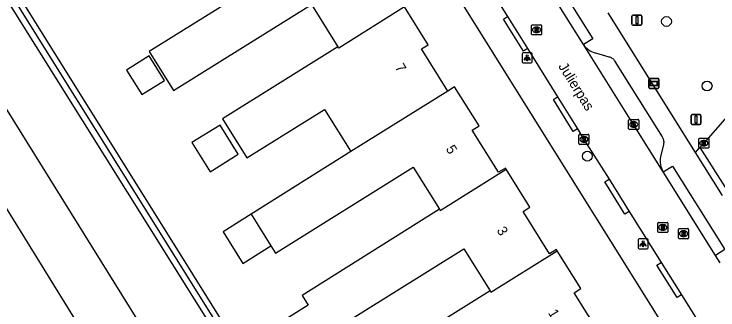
# Model space of a CAD drawing. Extents: x 158838 to 160074, y 386376 to 387776.
# Drawn here: x 159122.1 to 159192.2, y 386846.6 to 386876.1 of the extents above; entities that cross this region are included whole.
import ezdxf

# ---------------------------------------------------------------- set-up
doc = ezdxf.new("R2010")
doc.units = 0
for name, color, linetype in [('IMGEO_Afsluitpaal', 7, 'Continuous'), ('IMGEO_Berm_groen', 7, 'Continuous'), ('IMGEO_Boom', 7, 'Continuous'), ('IMGEO_Groenvoorziening', 7, 'Continuous'), ('IMGEO_Kolk', 7, 'Continuous'), ('IMGEO_Lichtpunt', 7, 'Continuous'), ('IMGEO_Openbare_ruimte_label', 7, 'Continuous'), ('IMGEO_Pand', 7, 'Continuous'), ('IMGEO_Pand_nummerreeks', 7, 'Continuous'), ('IMGEO_Rijbaan_lokaal_open', 7, 'Continuous'), ('IMGEO_Rioolput', 7, 'Continuous'), ('IMGEO_Straatnaambord', 7, 'Continuous'), ('IMGEO_Voetpad_open', 7, 'Continuous')]:
    doc.layers.add(name, color=color, linetype=linetype)

msp = doc.modelspace()

# ---------------------------------------------------------------- linework, layer by layer
at = {"layer": 'IMGEO_Afsluitpaal'}
for p, q in [((159183.612, 386875.093), (159183.612, 386875.893)), ((159183.612, 386875.893), (159183.612, 386875.093)), ((159183.712, 386875.993), (159184.502, 386875.993)), ((159184.502, 386875.993), (159183.712, 386875.993)), ((159184.602, 386875.893), (159184.602, 386875.093)), ((159184.602, 386875.093), (159184.602, 386875.893)), ((159184.502, 386874.993), (159183.712, 386874.993)), ((159183.712, 386874.993), (159184.502, 386874.993)), ((159189.493, 386865.198), (159189.493, 386865.998)), ((159189.493, 386865.998), (159189.493, 386865.198)), ((159189.593, 386866.098), (159190.383, 386866.098)), ((159190.383, 386866.098), (159189.593, 386866.098)), ((159190.483, 386865.998), (159190.483, 386865.198)), ((159190.483, 386865.198), (159190.483, 386865.998)), ((159190.383, 386865.098), (159189.593, 386865.098)), ((159189.593, 386865.098), (159190.383, 386865.098))]:
    msp.add_line(p, q, dxfattribs=at)
for points in [[(159184.032, 386875.868), (159184.182, 386875.868), (159184.182, 386875.118), (159184.032, 386875.118), (159184.032, 386875.868)], [(159189.913, 386865.973), (159190.063, 386865.973), (159190.063, 386865.223), (159189.913, 386865.223), (159189.913, 386865.973)]]:
    msp.add_lwpolyline(points, dxfattribs=at)
for centre, start, end in [((159183.712, 386875.893), 90, 180), ((159183.712, 386875.893), 90, 180), ((159184.502, 386875.893), 0, 90), ((159184.502, 386875.893), 360, 90), ((159183.712, 386875.093), 180, 270), ((159183.712, 386875.093), 180, 270), ((159184.502, 386875.093), 270, 0), ((159184.502, 386875.093), 270, 0), ((159189.593, 386865.998), 90, 180), ((159189.593, 386865.998), 90, 180), ((159190.383, 386865.998), 0, 90), ((159190.383, 386865.998), 360, 90), ((159189.593, 386865.198), 180, 270), ((159189.593, 386865.198), 180, 270), ((159190.383, 386865.198), 270, 0), ((159190.383, 386865.198), 270, 0)]:
    msp.add_arc(centre, 0.1, start, end, dxfattribs=at)
at = {"layer": 'IMGEO_Berm_groen'}
for points in [[(159123.048, 386814.194), (159142.528, 386822.4), (159089.158, 386908.868), (159070.867, 386896.72), (159109.025, 386833.71), (159123.048, 386814.194)], [(159096.401, 386906.705), (159148.14, 386823.428)]]:
    msp.add_lwpolyline(points, dxfattribs=at)
at = {"layer": 'IMGEO_Boom'}
for centre in [(159187.048, 386875.362), (159191.091, 386868.94), (159179.16, 386861.946)]:
    msp.add_circle(centre, 0.489, dxfattribs=at)
at = {"layer": 'IMGEO_Groenvoorziening'}
for points in [[(159153.383, 386826.367), (159102.052, 386908.422), (159101.832, 386908.935), (159101.604, 386909.612), (159101.437, 386910.307), (159101.332, 386911.014), (159101.291, 386911.728), (159101.315, 386912.442), (159101.402, 386913.152), (159101.551, 386913.851), (159101.763, 386914.534), (159102.035, 386915.195), (159102.365, 386915.829)], [(159102.915, 386915.575), (159102.608, 386914.992), (159102.355, 386914.384), (159102.156, 386913.756), (159102.015, 386913.113), (159101.932, 386912.46), (159101.907, 386911.802), (159101.941, 386911.144), (159102.034, 386910.492), (159102.185, 386909.851), (159102.393, 386909.226), (159102.615, 386908.705), (159154.046, 386826.389)], [(159154.526, 386826.749), (159103.157, 386908.962)]]:
    msp.add_lwpolyline(points, dxfattribs=at)
at = {"layer": 'IMGEO_Kolk'}
for p, q in [((159183.28, 386864.681), (159183.28, 386865.533)), ((159183.355, 386865.607), (159184.207, 386865.607)), ((159183.768, 386865.387), (159183.793, 386865.387)), ((159184.281, 386865.533), (159184.281, 386864.681)), ((159184.207, 386864.607), (159183.355, 386864.607)), ((159183.791, 386864.827), (159183.766, 386864.827)), ((159178.327, 386863.192), (159178.327, 386864.044)), ((159178.402, 386864.118), (159179.254, 386864.118)), ((159178.815, 386863.898), (159178.84, 386863.898)), ((159179.328, 386864.044), (159179.328, 386863.192)), ((159178.838, 386863.338), (159178.813, 386863.338)), ((159190.267, 386862.813), (159190.267, 386863.665)), ((159190.342, 386863.739), (159191.194, 386863.739)), ((159190.755, 386863.519), (159190.78, 386863.519)), ((159191.268, 386863.665), (159191.268, 386862.813)), ((159179.254, 386863.118), (159178.402, 386863.118)), ((159191.194, 386862.739), (159190.342, 386862.739)), ((159190.778, 386862.959), (159190.753, 386862.959))]:
    msp.add_line(p, q, dxfattribs=at)
for points in [[(159183.28, 386864.681), (159183.28, 386865.533)], [(159183.355, 386865.607), (159184.207, 386865.607)], [(159183.601, 386865.307), (159183.724, 386865.307), (159183.724, 386865.156), (159183.854, 386865.307), (159184.018, 386865.307), (159183.872, 386865.156), (159184.025, 386864.907), (159183.873, 386864.907), (159183.788, 386865.071), (159183.724, 386865.004), (159183.724, 386864.907), (159183.601, 386864.907), (159183.601, 386865.307)], [(159184.281, 386865.533), (159184.281, 386864.681)], [(159184.207, 386864.607), (159183.355, 386864.607)], [(159178.327, 386863.192), (159178.327, 386864.044)], [(159178.402, 386864.118), (159179.254, 386864.118)], [(159179.328, 386864.044), (159179.328, 386863.192)], [(159178.648, 386863.818), (159178.771, 386863.818), (159178.771, 386863.667), (159178.901, 386863.818), (159179.065, 386863.818), (159178.919, 386863.667), (159179.072, 386863.418), (159178.92, 386863.418), (159178.835, 386863.582), (159178.771, 386863.515), (159178.771, 386863.418), (159178.648, 386863.418), (159178.648, 386863.818)], [(159190.267, 386862.813), (159190.267, 386863.665)], [(159190.342, 386863.739), (159191.194, 386863.739)], [(159190.588, 386863.439), (159190.711, 386863.439), (159190.711, 386863.288), (159190.841, 386863.439), (159191.005, 386863.439), (159190.859, 386863.288), (159191.012, 386863.039), (159190.86, 386863.039), (159190.775, 386863.203), (159190.711, 386863.136), (159190.711, 386863.039), (159190.588, 386863.039), (159190.588, 386863.439)], [(159191.268, 386863.665), (159191.268, 386862.813)], [(159179.254, 386863.118), (159178.402, 386863.118)], [(159191.194, 386862.739), (159190.342, 386862.739)]]:
    msp.add_lwpolyline(points, dxfattribs=at)
for centre, start, end in [((159183.357, 386865.531), 91.55205, 178.44795), ((159183.357, 386865.531), 91.55205, 178.44795), ((159184.205, 386865.531), 1.55205, 88.44795), ((159184.205, 386865.531), 1.55205, 88.44795), ((159183.357, 386864.683), 181.55205, 268.44795), ((159183.357, 386864.683), 181.55205, 268.44795), ((159184.205, 386864.683), 271.55205, 358.44795), ((159184.205, 386864.683), 271.55205, 358.44795), ((159178.404, 386864.042), 91.55205, 178.44795), ((159178.404, 386864.042), 91.55205, 178.44795), ((159179.252, 386864.042), 1.55205, 88.44795), ((159179.252, 386864.042), 1.55205, 88.44795), ((159178.404, 386863.194), 181.55205, 268.44795), ((159178.404, 386863.194), 181.55205, 268.44795), ((159179.252, 386863.194), 271.55205, 358.44795), ((159179.252, 386863.194), 271.55205, 358.44795), ((159190.344, 386863.663), 91.55205, 178.44795), ((159190.344, 386863.663), 91.55205, 178.44795), ((159191.192, 386863.663), 1.55205, 88.44795), ((159191.192, 386863.663), 1.55205, 88.44795), ((159190.344, 386862.815), 181.55205, 268.44795), ((159190.344, 386862.815), 181.55205, 268.44795), ((159191.192, 386862.815), 271.55205, 358.44795), ((159191.192, 386862.815), 271.55205, 358.44795)]:
    msp.add_arc(centre, 0.0765, start, end, dxfattribs=at)
for centre, major_axis, ratio, start_param, end_param in [((159183.767, 386865.107), (-0.387, 0.002), 0.722429, 4.712389, 7.853982), ((159183.792, 386865.107), (-0.39, 0.002), 0.717154, 1.570796, 4.712389), ((159178.814, 386863.618), (-0.387, 0.002), 0.722429, 4.712389, 7.853982), ((159178.839, 386863.618), (-0.39, 0.002), 0.717154, 1.570796, 4.712389), ((159190.754, 386863.239), (-0.387, 0.002), 0.722429, 4.712389, 7.853982), ((159190.779, 386863.239), (-0.39, 0.002), 0.717154, 1.570796, 4.712389)]:
    msp.add_ellipse(centre, major_axis=major_axis, ratio=ratio, start_param=start_param, end_param=end_param, dxfattribs=at)
at = {"layer": 'IMGEO_Lichtpunt'}
for p, q in [((159172.676, 386872.151), (159172.676, 386871.344)), ((159172.676, 386872.151), (159172.676, 386871.344)), ((159173.578, 386872.246), (159172.77, 386872.246)), ((159173.578, 386872.246), (159172.77, 386872.246)), ((159173.672, 386871.344), (159173.672, 386872.151)), ((159173.672, 386871.344), (159173.672, 386872.151)), ((159172.77, 386871.25), (159173.578, 386871.25)), ((159172.77, 386871.25), (159173.578, 386871.25)), ((159184.216, 386853.616), (159184.216, 386852.809)), ((159184.216, 386853.616), (159184.216, 386852.809)), ((159185.118, 386853.711), (159184.31, 386853.711)), ((159185.118, 386853.711), (159184.31, 386853.711)), ((159185.212, 386852.809), (159185.212, 386853.616)), ((159185.212, 386852.809), (159185.212, 386853.616)), ((159184.31, 386852.715), (159185.118, 386852.715)), ((159184.31, 386852.715), (159185.118, 386852.715))]:
    msp.add_line(p, q, dxfattribs=at)
for points in [[(159173.05, 386871.815), (159173.089, 386871.787), (159172.901, 386871.525), (159172.863, 386871.552), (159173.05, 386871.815)], [(159173.152, 386871.767), (159173.199, 386871.767), (159173.199, 386871.445), (159173.152, 386871.445), (159173.152, 386871.767)], [(159173.262, 386871.787), (159173.3, 386871.814), (159173.487, 386871.552), (159173.448, 386871.524), (159173.262, 386871.787)], [(159184.59, 386853.28), (159184.629, 386853.252), (159184.441, 386852.99), (159184.403, 386853.017), (159184.59, 386853.28)], [(159184.692, 386853.232), (159184.739, 386853.232), (159184.739, 386852.91), (159184.692, 386852.91), (159184.692, 386853.232)], [(159184.802, 386853.252), (159184.84, 386853.279), (159185.027, 386853.017), (159184.988, 386852.989), (159184.802, 386853.252)]]:
    msp.add_lwpolyline(points, dxfattribs=at)
for centre in [(159173.175, 386871.949), (159184.715, 386853.414)]:
    msp.add_circle(centre, 0.0994, dxfattribs=at)
for centre, start, end in [((159172.77, 386872.151), 90, 180), ((159172.77, 386872.151), 90, 180), ((159173.578, 386872.151), 0, 90), ((159173.578, 386872.151), 0, 90), ((159172.77, 386871.344), 180, 270), ((159172.77, 386871.344), 180, 270), ((159173.578, 386871.344), 270, 0), ((159173.578, 386871.344), 270, 360), ((159184.31, 386853.616), 90, 180), ((159184.31, 386853.616), 90, 180), ((159185.118, 386853.616), 0, 90), ((159185.118, 386853.616), 0, 90), ((159184.31, 386852.809), 180, 270), ((159184.31, 386852.809), 180, 270), ((159185.118, 386852.809), 270, 0), ((159185.118, 386852.809), 270, 360)]:
    msp.add_arc(centre, 0.0946, start, end, dxfattribs=at)
at = {"layer": 'IMGEO_Pand'}
for points in [[(159145.507, 386878.611), (159135.531, 386872.387), (159137.969, 386868.478), (159151.702, 386877.045), (159154.326, 386872.839)], [(159160.97, 386876.826), (159154.405, 386872.712), (159154.326, 386872.839)], [(159165.273, 386868.43), (159162.65, 386872.628), (159163.328, 386873.052), (159160.97, 386876.826)], [(159154.326, 386872.839), (159142.837, 386865.671), (159145.266, 386861.776), (159152.998, 386866.598), (159155.617, 386862.398)], [(159133.274, 386870.529), (159134.8, 386868.082), (159137.072, 386869.5), (159135.547, 386871.946), (159133.274, 386870.529)], [(159171.085, 386860.636), (159171.006, 386860.763), (159170.328, 386860.339), (159167.71, 386864.529), (159168.389, 386864.953), (159165.951, 386868.854), (159165.273, 386868.43)], [(159165.273, 386868.43), (159155.617, 386862.398)], [(159139.788, 386863.293), (159141.596, 386860.395), (159144.407, 386862.148), (159142.599, 386865.046), (159139.788, 386863.293)], [(159155.617, 386862.398), (159145.682, 386856.168)], [(159147.661, 386853.011), (159148.125, 386852.271), (159161.806, 386860.849), (159164.435, 386856.656)], [(159164.435, 386856.656), (159164.515, 386856.529), (159171.085, 386860.636)], [(159176.157, 386852.519), (159176.078, 386852.646), (159175.399, 386852.222), (159172.765, 386856.438), (159173.444, 386856.861), (159171.085, 386860.636)], [(159145.682, 386856.168), (159142.885, 386854.414), (159144.865, 386851.257), (159147.661, 386853.011)], [(159145.682, 386856.168), (159147.661, 386853.011)], [(159164.435, 386856.656), (159150.754, 386848.078), (159151.373, 386847.087), (159147.435, 386844.627), (159149.247, 386841.726), (159153.185, 386844.185), (159166.854, 386852.721), (159169.477, 386848.522)], [(159169.477, 386848.522), (159152.42, 386837.864), (159154.125, 386835.138), (159157.511, 386837.252), (159158.246, 386836.076), (159171.909, 386844.608), (159174.674, 386840.154), (159180.627, 386843.874), (159177.845, 386848.326), (159178.515, 386848.745), (159176.157, 386852.519)], [(159169.477, 386848.522), (159169.557, 386848.395), (159176.157, 386852.519)]]:
    msp.add_lwpolyline(points, dxfattribs=at)
at = {"layer": 'IMGEO_Rijbaan_lokaal_open'}
for points in [[(159222.579, 386900.042), (159222.46, 386899.698), (159222.248, 386899.343), (159190.765, 386863.238), (159190.378, 386862.801)], [(159168.115, 386880.832), (159168.528, 386880.16), (159171.227, 386875.856)], [(159178.788, 386873.065), (159173.593, 386881.353)], [(159171.227, 386875.856), (159173.222, 386872.666)], [(159186.711, 386860.373), (159183.776, 386865.106), (159178.788, 386873.065)], [(159173.222, 386872.666), (159176.205, 386867.861)], [(159176.205, 386867.861), (159178.182, 386864.676)], [(159178.182, 386864.676), (159178.825, 386863.619), (159181.339, 386859.642)], [(159189.931, 386862.296), (159190.378, 386862.801)], [(159190.378, 386862.801), (159193.08, 386858.53)], [(159192.634, 386858.019), (159189.931, 386862.296)], [(159191.923, 386852.046), (159186.711, 386860.373)], [(159181.339, 386859.642), (159183.336, 386856.441)], [(159183.336, 386856.441), (159186.514, 386851.338)], [(159192.391, 386851.32), (159191.923, 386852.046)], [(159186.514, 386851.338), (159188.529, 386848.144)], [(159188.529, 386848.144), (159190.768, 386844.567), (159203.199, 386824.618), (159213.548, 386808.108), (159218.217, 386800.643), (159218.869, 386799.586)]]:
    msp.add_lwpolyline(points, dxfattribs=at)
at = {"layer": 'IMGEO_Rioolput'}
for p, q in [((159173.607, 386874.104), (159173.607, 386874.956)), ((159173.682, 386875.03), (159174.534, 386875.03)), ((159174.095, 386874.81), (159174.12, 386874.81)), ((159174.608, 386874.956), (159174.608, 386874.104)), ((159174.534, 386874.03), (159173.682, 386874.03)), ((159174.118, 386874.25), (159174.093, 386874.25)), ((159186.179, 386854.422), (159186.179, 386855.274)), ((159186.254, 386855.348), (159187.106, 386855.348)), ((159186.667, 386855.128), (159186.692, 386855.128)), ((159187.18, 386855.274), (159187.18, 386854.422)), ((159187.106, 386854.348), (159186.254, 386854.348)), ((159186.69, 386854.568), (159186.665, 386854.568)), ((159188.243, 386853.797), (159188.243, 386854.649)), ((159188.318, 386854.723), (159189.17, 386854.723)), ((159188.731, 386854.503), (159188.756, 386854.503)), ((159189.244, 386854.649), (159189.244, 386853.797)), ((159189.17, 386853.723), (159188.318, 386853.723)), ((159188.754, 386853.943), (159188.729, 386853.943))]:
    msp.add_line(p, q, dxfattribs=at)
for points in [[(159173.607, 386874.104), (159173.607, 386874.956)], [(159173.682, 386875.03), (159174.534, 386875.03)], [(159174.196, 386874.728), (159173.944, 386874.73), (159173.944, 386874.33)], [(159173.944, 386874.33), (159174.068, 386874.33), (159174.068, 386874.492), (159174.079, 386874.492)], [(159174.122, 386874.649), (159174.068, 386874.649), (159174.068, 386874.568)], [(159174.068, 386874.568), (159174.12, 386874.568)], [(159174.126, 386874.463), (159174.197, 386874.33), (159174.337, 386874.33), (159174.272, 386874.456)], [(159174.608, 386874.956), (159174.608, 386874.104)], [(159174.534, 386874.03), (159173.682, 386874.03)], [(159186.179, 386854.422), (159186.179, 386855.274)], [(159186.254, 386855.348), (159187.106, 386855.348)], [(159186.768, 386855.046), (159186.516, 386855.048), (159186.516, 386854.648)], [(159186.516, 386854.648), (159186.64, 386854.648), (159186.64, 386854.81), (159186.651, 386854.81)], [(159186.694, 386854.967), (159186.64, 386854.967), (159186.64, 386854.886)], [(159186.64, 386854.886), (159186.692, 386854.886)], [(159186.698, 386854.781), (159186.769, 386854.648), (159186.909, 386854.648), (159186.844, 386854.774)], [(159187.18, 386855.274), (159187.18, 386854.422)], [(159187.106, 386854.348), (159186.254, 386854.348)], [(159188.243, 386853.797), (159188.243, 386854.649)], [(159188.318, 386854.723), (159189.17, 386854.723)], [(159188.832, 386854.421), (159188.58, 386854.423), (159188.58, 386854.023)], [(159188.58, 386854.023), (159188.704, 386854.023), (159188.704, 386854.185), (159188.715, 386854.185)], [(159188.758, 386854.342), (159188.704, 386854.342), (159188.704, 386854.261)], [(159188.704, 386854.261), (159188.756, 386854.261)], [(159188.762, 386854.156), (159188.833, 386854.023), (159188.973, 386854.023), (159188.908, 386854.149)], [(159189.244, 386854.649), (159189.244, 386853.797)], [(159189.17, 386853.723), (159188.318, 386853.723)]]:
    msp.add_lwpolyline(points, dxfattribs=at)
for centre, radius, start, end in [((159173.684, 386874.954), 0.0765, 91.55205, 178.44795), ((159173.684, 386874.954), 0.0765, 91.55205, 178.44795), ((159174.078, 386874.439), 0.0533, 26.02933, 88.69889), ((159174.104, 386874.757), 0.19, 274.7715, 282.96867), ((159174.128, 386874.553), 0.0964, 77.00612, 93.18647), ((159174.142, 386874.61), 0.0378, 276.66336, 79.67722), ((159174.195, 386874.618), 0.109, 350.36119, 89.41601), ((159174.193, 386874.618), 0.112, 277.58423, 350.98172), ((159174.177, 386874.403), 0.108, 29.51342, 73.79051), ((159174.532, 386874.954), 0.0765, 1.55205, 88.44795), ((159174.532, 386874.954), 0.0765, 1.55205, 88.44795), ((159173.684, 386874.106), 0.0765, 181.55205, 268.44795), ((159173.684, 386874.106), 0.0765, 181.55205, 268.44795), ((159174.532, 386874.106), 0.0765, 271.55205, 358.44795), ((159174.532, 386874.106), 0.0765, 271.55205, 358.44795), ((159186.256, 386855.272), 0.0765, 91.55205, 178.44795), ((159186.256, 386855.272), 0.0765, 91.55205, 178.44795), ((159186.65, 386854.757), 0.0533, 26.02933, 88.69889), ((159186.676, 386855.075), 0.19, 274.7715, 282.96867), ((159186.7, 386854.871), 0.0964, 77.00612, 93.18647), ((159186.714, 386854.928), 0.0378, 276.66336, 79.67722), ((159186.767, 386854.936), 0.109, 350.36119, 89.41601), ((159186.765, 386854.936), 0.112, 277.58423, 350.98172), ((159186.749, 386854.721), 0.108, 29.51342, 73.79051), ((159187.104, 386855.272), 0.0765, 1.55205, 88.44795), ((159187.104, 386855.272), 0.0765, 1.55205, 88.44795), ((159186.256, 386854.424), 0.0765, 181.55205, 268.44795), ((159186.256, 386854.424), 0.0765, 181.55205, 268.44795), ((159187.104, 386854.424), 0.0765, 271.55205, 358.44795), ((159187.104, 386854.424), 0.0765, 271.55205, 358.44795), ((159188.32, 386854.647), 0.0765, 91.55205, 178.44795), ((159188.32, 386854.647), 0.0765, 91.55205, 178.44795), ((159188.714, 386854.132), 0.0533, 26.02933, 88.69889), ((159188.74, 386854.45), 0.19, 274.7715, 282.96867), ((159188.764, 386854.246), 0.0964, 77.00612, 93.18647), ((159188.778, 386854.303), 0.0378, 276.66336, 79.67722), ((159188.831, 386854.311), 0.109, 350.36119, 89.41601), ((159188.829, 386854.311), 0.112, 277.58423, 350.98172), ((159188.813, 386854.096), 0.108, 29.51342, 73.79051), ((159189.168, 386854.647), 0.0765, 1.55205, 88.44795), ((159189.168, 386854.647), 0.0765, 1.55205, 88.44795), ((159188.32, 386853.799), 0.0765, 181.55205, 268.44795), ((159188.32, 386853.799), 0.0765, 181.55205, 268.44795), ((159189.168, 386853.799), 0.0765, 271.55205, 358.44795), ((159189.168, 386853.799), 0.0765, 271.55205, 358.44795)]:
    msp.add_arc(centre, radius, start, end, dxfattribs=at)
for centre, major_axis, ratio, start_param, end_param in [((159174.094, 386874.53), (-0.387, 0.002), 0.722429, 4.712389, 7.853982), ((159174.119, 386874.53), (-0.39, 0.002), 0.717154, 1.570796, 4.712389), ((159186.666, 386854.848), (-0.387, 0.002), 0.722429, 4.712389, 7.853982), ((159186.691, 386854.848), (-0.39, 0.002), 0.717154, 1.570796, 4.712389), ((159188.73, 386854.223), (-0.387, 0.002), 0.722429, 4.712389, 7.853982), ((159188.755, 386854.223), (-0.39, 0.002), 0.717154, 1.570796, 4.712389)]:
    msp.add_ellipse(centre, major_axis=major_axis, ratio=ratio, start_param=start_param, end_param=end_param, dxfattribs=at)
at = {"layer": 'IMGEO_Straatnaambord'}
for p, q in [((159185.286, 386868.796), (159185.286, 386869.596)), ((159185.286, 386869.596), (159185.286, 386868.796)), ((159185.386, 386869.696), (159186.176, 386869.696)), ((159186.176, 386869.696), (159185.386, 386869.696)), ((159186.276, 386869.596), (159186.276, 386868.796)), ((159186.276, 386868.796), (159186.276, 386869.596)), ((159186.176, 386868.696), (159185.386, 386868.696)), ((159185.386, 386868.696), (159186.176, 386868.696))]:
    msp.add_line(p, q, dxfattribs=at)
for points in [[(159185.387, 386869.428), (159186.175, 386869.428), (159186.175, 386868.964), (159185.387, 386868.964), (159185.387, 386869.428)], [(159185.452, 386869.363), (159185.452, 386869.029), (159186.11, 386869.029), (159186.11, 386869.363), (159185.452, 386869.363)]]:
    msp.add_lwpolyline(points, dxfattribs=at)
for centre, start, end in [((159185.386, 386869.596), 90, 180), ((159185.386, 386869.596), 90, 180), ((159186.176, 386869.596), 0, 90), ((159186.176, 386869.596), 360, 90), ((159185.386, 386868.796), 180, 270), ((159185.386, 386868.796), 180, 270), ((159186.176, 386868.796), 270, 0), ((159186.176, 386868.796), 270, 0)]:
    msp.add_arc(centre, 0.1, start, end, dxfattribs=at)
at = {"layer": 'IMGEO_Voetpad_open'}
for points in [[(159133.211, 386927.185), (159133.374, 386927.263), (159133.544, 386927.327), (159133.719, 386927.374), (159133.897, 386927.406), (159134.078, 386927.422), (159134.259, 386927.421), (159134.439, 386927.405), (159134.618, 386927.372), (159134.792, 386927.324), (159134.962, 386927.26), (159135.125, 386927.181), (159135.281, 386927.088), (159135.427, 386926.982), (159135.564, 386926.863), (159135.689, 386926.732), (159135.802, 386926.59), (159135.902, 386926.439), (159153.24, 386898.677), (159187.007, 386844.595), (159190.588, 386838.84)], [(159177.122, 386877.793), (159179.72, 386873.649), (159178.788, 386873.065)], [(159173.222, 386872.666), (159172.799, 386872.401), (159170.804, 386875.591), (159171.227, 386875.856)], [(159189.931, 386862.296), (159181.238, 386876.212)], [(159178.788, 386873.065), (159178.893, 386872.92), (159179.011, 386872.785), (159179.14, 386872.661), (159179.28, 386872.549), (159179.43, 386872.45), (159179.587, 386872.365), (159179.752, 386872.294), (159179.922, 386872.239), (159179.969, 386872.226), (159181.311, 386871.858), (159181.385, 386871.835), (159181.466, 386871.802), (159181.545, 386871.762), (159181.619, 386871.714), (159181.689, 386871.661), (159181.754, 386871.601), (159181.813, 386871.536), (159181.866, 386871.466), (159181.913, 386871.391), (159186.621, 386863.86), (159186.644, 386863.82), (159186.684, 386863.739), (159186.717, 386863.654), (159186.742, 386863.567), (159186.759, 386863.478), (159186.768, 386863.388), (159186.768, 386863.297), (159186.761, 386863.207), (159186.746, 386863.118), (159186.463, 386861.878), (159186.433, 386861.689), (159186.42, 386861.499), (159186.424, 386861.308), (159186.446, 386861.118), (159186.484, 386860.931), (159186.538, 386860.748), (159186.609, 386860.571), (159186.695, 386860.4), (159186.711, 386860.373)], [(159178.182, 386864.676), (159177.758, 386864.413), (159175.781, 386867.598), (159176.205, 386867.861)], [(159186.711, 386860.373), (159187.643, 386860.957), (159192.855, 386852.63), (159191.923, 386852.046)], [(159183.336, 386856.441), (159182.912, 386856.177), (159180.915, 386859.378), (159181.339, 386859.642)], [(159188.529, 386848.144), (159188.107, 386847.878), (159186.092, 386851.072), (159186.514, 386851.338)]]:
    msp.add_lwpolyline(points, dxfattribs=at)

# ---------------------------------------------------------------- texts
at = {"layer": 'IMGEO_Openbare_ruimte_label'}
msp.add_text('Julierpas', height=1, rotation=302.00538, dxfattribs=at).set_placement((159176.236, 386870.901))
at = {"layer": 'IMGEO_Pand_nummerreeks'}
for s, rotation, p in [('7', 301.96012, (159159.968, 386870.791)), ('5', 301.95938, (159165.034, 386862.671)), ('3', 301.95938, (159170.1, 386854.552)), ('1', 301.96012, (159175.226, 386846.335))]:
    msp.add_text(s, height=1, rotation=rotation, dxfattribs=at).set_placement(p)

doc.saveas('drawing.dxf')
